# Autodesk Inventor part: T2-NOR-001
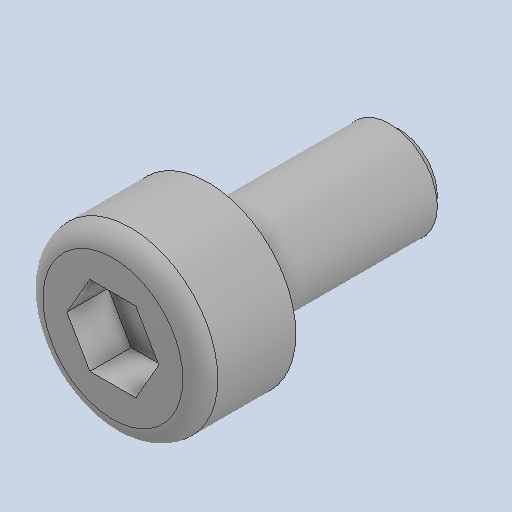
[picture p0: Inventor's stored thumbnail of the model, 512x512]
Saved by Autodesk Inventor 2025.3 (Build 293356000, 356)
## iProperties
Created: 2020-02
Part Number: T2-NOR-001
Material: Genérico
Description: Tornillo de cabeza cilíndrica con hexágono interior M3 × 6 mm
Document SubType Name: Modeling
Designer: Luis MuÃ±oz
Authority: Unknown
Density: 1 g/cm^3
Appearance: Valor por defecto
Project: TESIS 2 - Plataforma mecatrÃ³nica preventiva desacoplada
Sending System: FreeCAD
Preprocessor: Open CASCADE STEP processor 7.3
Title: Tornillo de cabeza cilÃ­ndrica con hexÃ¡gono interior M3 Ã— 6 mm
Author: Author
Revision Number: 00
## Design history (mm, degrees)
feature "Base1"
node "Sólido1"
